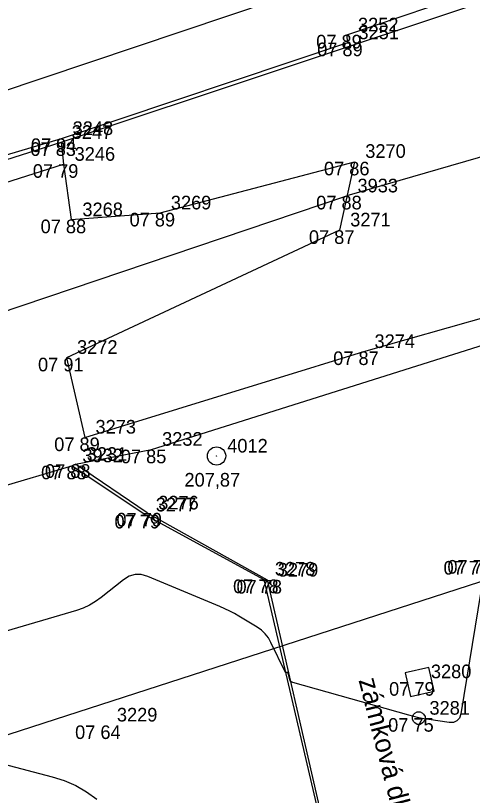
# Model space of a CAD drawing. Extents: x -703403 to -701924, y -1022520 to -1021856.
# Drawn here: x -702448.68 to -702439.29, y -1022331.73 to -1022315.69 of the extents above; entities that cross this region are included whole.
import ezdxf

# ---------------------------------------------------------------- set-up
doc = ezdxf.new("R2010")
doc.units = 0
for name, color, linetype in [('Ex_Minor Contours', 7, 'Continuous'), ('Z_bodove_pole', 7, 'Continuous'), ('Z_bodove_pole_cisla', 7, 'Continuous'), ('Z_bodove_pole_vysky', 7, 'Continuous'), ('Z_body', 7, 'Continuous'), ('Z_body_cisla', 7, 'Continuous'), ('Z_body_vysky_redukovane', 7, 'Continuous'), ('Z_chodnik', 7, 'Continuous'), ('Z_katastr_hranice', 7, 'Continuous'), ('Z_komunikace', 7, 'Continuous'), ('Z_komunikace_osa', 7, 'Continuous'), ('Z_obruba', 7, 'Continuous'), ('Z_popisy', 7, 'Continuous'), ('Z_rozhranni', 7, 'Continuous'), ('Z_site_nerozlisene_znaky', 7, 'Continuous'), ('Z_site_vodovod_znaky', 7, 'Continuous')]:
    doc.layers.add(name, color=color, linetype=linetype)

# ---------------------------------------------------------------- blocks, each defined once
blk = doc.blocks.new('POINT_DISPLAY')
blk.add_line((0, 0), (0, 0))
blk = doc.blocks.new('Z614')
for p, q in [((-0.13, 0.03), (-0.1, 0.08)), ((-0.13, -0.03), (-0.13, 0.03)), ((-0.1, 0.08), (-0.08, 0.1)), ((-0.08, 0.1), (-0.03, 0.13)), ((-0.03, 0.13), (0.03, 0.13)), ((0.03, 0.13), (0.08, 0.1)), ((0.08, 0.1), (0.1, 0.08)), ((0.1, 0.08), (0.13, 0.03)), ((0.13, 0.03), (0.13, -0.03)), ((-0.1, -0.08), (-0.13, -0.03)), ((-0.08, -0.1), (-0.1, -0.08)), ((-0.03, -0.13), (-0.08, -0.1)), ((0.03, -0.13), (-0.03, -0.13)), ((0.08, -0.1), (0.03, -0.13)), ((0.1, -0.08), (0.08, -0.1)), ((0.13, -0.03), (0.1, -0.08))]:
    blk.add_line(p, q)
blk = doc.blocks.new('Z608')
for p, q in [((0.25, 0.25), (-0.25, 0.25)), ((-0.25, 0.25), (-0.25, -0.25)), ((0.25, -0.25), (0.25, 0.25)), ((-0.25, -0.25), (0.25, -0.25))]:
    blk.add_line(p, q)
blk = doc.blocks.new('Z101')
for radius in [0.188, 0.0025]:
    blk.add_circle((0, 0), radius)

msp = doc.modelspace()

# ---------------------------------------------------------------- linework, layer by layer
at = {"layer": 'Ex_Minor Contours'}
for points in [[(-702439.114, -1022327.534), (-702439.525, -1022330.051), (-702439.553, -1022330.14), (-702439.603, -1022330.199), (-702439.674, -1022330.229), (-702439.767, -1022330.229), (-702440.182, -1022330.17), (-702440.286, -1022330.153), (-702440.389, -1022330.133), (-702440.491, -1022330.11), (-702440.592, -1022330.083), (-702442.98, -1022329.407), (-702443.001, -1022329.399), (-702443.019, -1022329.386), (-702443.032, -1022329.368), (-702443.041, -1022329.347), (-702443.078, -1022329.219), (-702443.081, -1022329.213), (-702443.084, -1022329.209), (-702443.089, -1022329.206), (-702443.095, -1022329.205), (-702443.12, -1022329.201), (-702443.126, -1022329.199), (-702443.131, -1022329.197), (-702443.135, -1022329.193), (-702443.138, -1022329.188), (-702443.43, -1022328.583), (-702443.483, -1022328.49), (-702443.548, -1022328.407), (-702443.625, -1022328.335), (-702443.713, -1022328.273), (-702444.089, -1022328.046), (-702444.183, -1022327.991), (-702444.28, -1022327.94), (-702444.379, -1022327.892), (-702444.479, -1022327.848), (-702445.966, -1022327.227), (-702446.099, -1022327.189), (-702446.226, -1022327.188), (-702446.348, -1022327.224), (-702446.465, -1022327.297), (-702446.922, -1022327.661), (-702447.04, -1022327.745), (-702447.164, -1022327.818), (-702447.294, -1022327.878), (-702447.431, -1022327.926), (-702448.992, -1022328.388)], [(-702457.515, -1022332.317), (-702453.977, -1022331.609), (-702453.528, -1022331.523), (-702453.078, -1022331.445), (-702452.626, -1022331.374), (-702452.173, -1022331.311), (-702449.971, -1022331.021), (-702449.712, -1022330.999), (-702449.454, -1022331.003), (-702449.198, -1022331.031), (-702448.944, -1022331.084), (-702447.93, -1022331.348), (-702447.682, -1022331.426), (-702447.447, -1022331.529), (-702447.224, -1022331.656), (-702447.014, -1022331.808)]]:
    msp.add_lwpolyline(points, dxfattribs=at)
at = {"layer": 'Z_chodnik'}
for p, q in [((-702454.59, -1022319.15), (-702443.36, -1022315.37)), ((-702445.98, -1022325.92), (-702447.45, -1022324.92)), ((-702445.98, -1022325.92), (-702443.51, -1022327.3)), ((-702443.51, -1022327.3), (-702441.9, -1022334.28))]:
    msp.add_line(p, q, dxfattribs=at)
at = {"layer": 'Z_katastr_hranice'}
msp.add_line((-702432.63, -1022325.24), (-702461.35, -1022334.53), dxfattribs=at)
at = {"layer": 'Z_komunikace'}
for p, q in [((-702447.75, -1022318.3), (-702437.41, -1022314.85)), ((-702454.53, -1022320.44), (-702447.75, -1022318.3)), ((-702445.89, -1022324.62), (-702438.17, -1022322.18)), ((-702447.45, -1022324.92), (-702445.89, -1022324.62)), ((-702452.66, -1022326.47), (-702447.53, -1022324.95)), ((-702447.53, -1022324.95), (-702447.45, -1022324.92))]:
    msp.add_line(p, q, dxfattribs=at)
at = {"layer": 'Z_komunikace_osa'}
for p in [(-702436.36, -1022317.81), (-702453.47, -1022323.32)]:
    msp.add_line(p, (-702441.87, -1022319.4), dxfattribs=at)
at = {"layer": 'Z_obruba'}
for p, q in [((-702441.87, -1022316.09), (-702437.53, -1022314.62)), ((-702441.85, -1022316.25), (-702441.87, -1022316.09)), ((-702447.74, -1022318.22), (-702441.85, -1022316.25)), ((-702454.52, -1022320.23), (-702447.74, -1022318.22)), ((-702446.02, -1022325.96), (-702447.53, -1022324.95)), ((-702446.02, -1022325.96), (-702443.58, -1022327.29)), ((-702443.58, -1022327.29), (-702441.94, -1022334.29))]:
    msp.add_line(p, q, dxfattribs=at)
at = {"layer": 'Z_rozhranni'}
for p, q in [((-702447.75, -1022318.3), (-702447.7, -1022318.75)), ((-702454.37, -1022320.86), (-702447.7, -1022318.75)), ((-702447.7, -1022318.75), (-702447.54, -1022319.89)), ((-702445.71, -1022319.75), (-702441.71, -1022318.7)), ((-702441.71, -1022318.7), (-702442.02, -1022320.11)), ((-702447.54, -1022319.89), (-702445.71, -1022319.75)), ((-702442.02, -1022320.11), (-702447.64, -1022322.73)), ((-702441.52, -1022322.6), (-702437.86, -1022321.56)), ((-702447.26, -1022324.37), (-702441.52, -1022322.6)), ((-702447.64, -1022322.73), (-702447.26, -1022324.37))]:
    msp.add_line(p, q, dxfattribs=at)

# ---------------------------------------------------------------- block references
at = {"layer": 'Z_bodove_pole'}
msp.add_blockref('Z101', (-702444.55, -1022324.75), dxfattribs=at)
at = {"layer": 'Z_body'}
for p in [(-702441.87, -1022316.09), (-702441.85, -1022316.25), (-702447.75, -1022318.3), (-702447.74, -1022318.22), (-702447.7, -1022318.75), (-702441.71, -1022318.7), (-702441.87, -1022319.4), (-702445.71, -1022319.75), (-702447.54, -1022319.89), (-702442.02, -1022320.11), (-702441.52, -1022322.6), (-702447.64, -1022322.73), (-702447.26, -1022324.37), (-702445.89, -1022324.62), (-702444.55, -1022324.75), (-702447.53, -1022324.95), (-702447.45, -1022324.92), (-702446.02, -1022325.96), (-702445.98, -1022325.92), (-702443.58, -1022327.29), (-702443.51, -1022327.3), (-702440.37, -1022329.4), (-702440.39, -1022330.14), (-702446.83, -1022330.29)]:
    msp.add_blockref('POINT_DISPLAY', p, dxfattribs=at)
at = {"layer": 'Z_site_nerozlisene_znaky', "rotation": 12.6}
msp.add_blockref('Z608', (-702440.37, -1022329.4), dxfattribs=at)
at = {"layer": 'Z_site_vodovod_znaky'}
msp.add_blockref('Z614', (-702440.39, -1022330.14), dxfattribs=at)

# ---------------------------------------------------------------- texts
at = {"layer": 'Z_bodove_pole_cisla'}
msp.add_text('4012', height=0.28, dxfattribs=at).set_placement((-702444.33, -1022324.68))
at = {"layer": 'Z_bodove_pole_vysky'}
msp.add_text('207,87', height=0.28, dxfattribs=at).set_placement((-702445.21, -1022325.38))
at = {"layer": 'Z_body_cisla'}
for s, p in [('3252', (-702441.64, -1022316.02)), ('3251', (-702441.63, -1022316.18)), ('3247', (-702447.53, -1022318.23)), ('3248', (-702447.51, -1022318.15)), ('3246', (-702447.47, -1022318.68)), ('3270', (-702441.49, -1022318.62)), ('3933', (-702441.65, -1022319.33)), ('3269', (-702445.49, -1022319.68)), ('3268', (-702447.31, -1022319.82)), ('3271', (-702441.8, -1022320.03)), ('3274', (-702441.3, -1022322.53)), ('3272', (-702447.42, -1022322.65)), ('3273', (-702447.04, -1022324.29)), ('3232', (-702445.67, -1022324.54)), ('3231', (-702447.22, -1022324.85)), ('3932', (-702447.31, -1022324.88)), ('3277', (-702445.8, -1022325.89)), ('3276', (-702445.75, -1022325.85)), ('3278', (-702443.35, -1022327.21)), ('3279', (-702443.29, -1022327.23)), ('3280', (-702440.14, -1022329.32)), ('3281', (-702440.17, -1022330.07)), ('3229', (-702446.6, -1022330.21))]:
    msp.add_text(s, height=0.28, dxfattribs=at).set_placement(p)
at = {"layer": 'Z_body_vysky_redukovane'}
for s, p in [('07 89', (-702442.5, -1022316.37)), ('07 89', (-702442.48, -1022316.53)), ('07 83', (-702448.38, -1022318.58)), ('07 94', (-702448.37, -1022318.5)), ('07 79', (-702448.33, -1022319.03)), ('07 86', (-702442.34, -1022318.98)), ('07 88', (-702442.5, -1022319.68)), ('07 89', (-702446.34, -1022320.03)), ('07 88', (-702448.17, -1022320.17)), ('07 87', (-702442.65, -1022320.39)), ('07 87', (-702442.15, -1022322.88)), ('07 91', (-702448.223, -1022323.01)), ('07 89', (-702447.89, -1022324.65)), ('07 85', (-702446.52, -1022324.9)), ('07 88', (-702448.16, -1022325.23)), ('07 88', (-702448.08, -1022325.2)), ('07 79', (-702446.65, -1022326.24)), ('07 79', (-702446.61, -1022326.2)), ('07 76', (-702439.88, -1022327.19)), ('07 76', (-702439.8, -1022327.17)), ('07 78', (-702444.21, -1022327.57)), ('07 78', (-702444.14, -1022327.58)), ('07 79', (-702441, -1022329.68)), ('07 75', (-702441.02, -1022330.42)), ('07 64', (-702447.46, -1022330.57))]:
    msp.add_text(s, height=0.28, dxfattribs=at).set_placement(p)
at = {"layer": 'Z_popisy'}
msp.add_text('zámková dlažba', height=0.4, rotation=284.4, dxfattribs=at).set_placement((-702441.63, -1022329.36))

doc.saveas('drawing.dxf')
